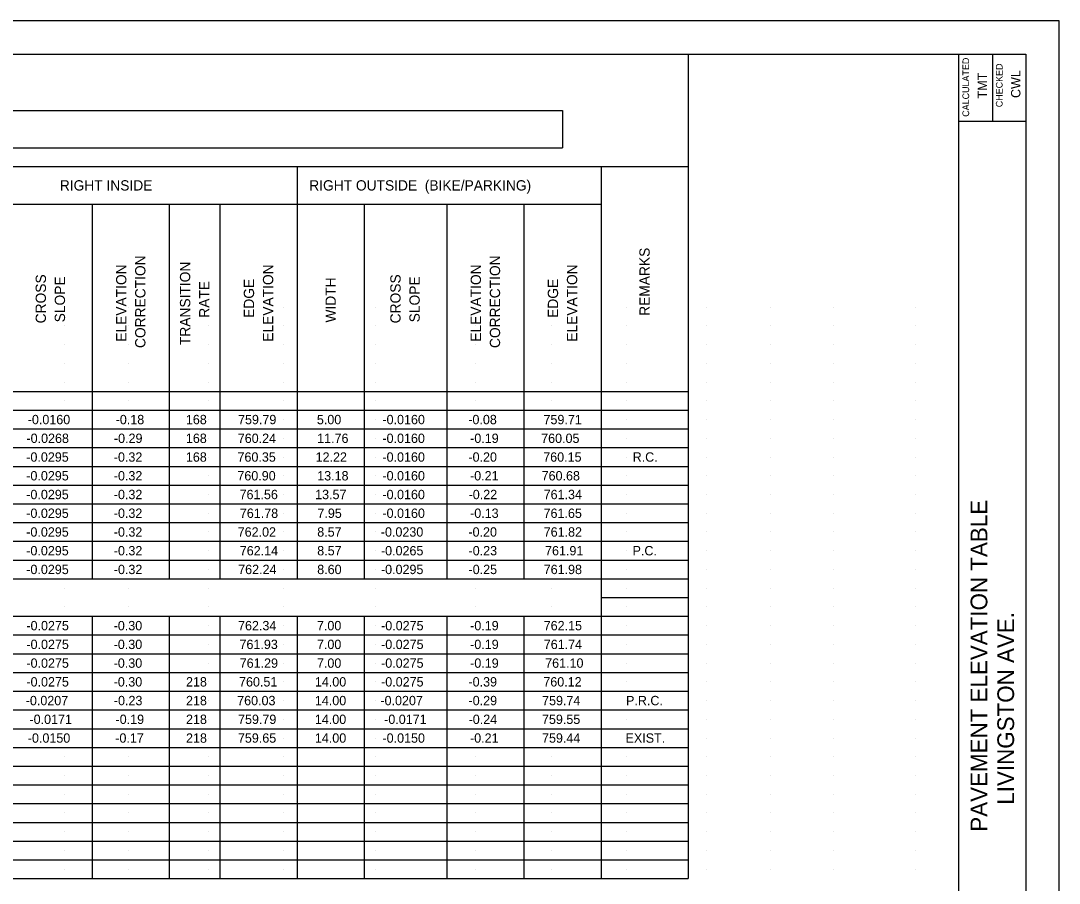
# Model space of a CAD drawing. Extents: x -15.4 to 18.6, y -12.6 to 9.4.
# Drawn here: x 3.11 to 18.64, y -3.5 to 9.39 of the extents above; entities that cross this region are included whole.
import ezdxf

# ---------------------------------------------------------------- set-up
doc = ezdxf.new("R2010")
doc.units = 0
for name, color, linetype in [('SH_Border', 7, 'Continuous'), ('SH_Cut_Line', 7, 'Continuous'), ('SH_Data', 7, 'Continuous'), ('SH_Text', 7, 'Continuous')]:
    doc.layers.add(name, color=color, linetype=linetype)

msp = doc.modelspace()

# ---------------------------------------------------------------- linework, layer by layer
at = {"layer": 'SH_Border'}
for p, q in [((17.143, -12.112), (17.143, 8.888)), ((17.643, 8.888), (17.643, 7.888)), ((17.143, 7.888), (18.143, 7.888))]:
    msp.add_line(p, q, dxfattribs=at)
msp.add_lwpolyline([(-13.357, 8.888), (18.143, 8.888), (18.143, -12.112), (-13.357, -12.112)], close=True, dxfattribs=at)
at = {"layer": 'SH_Cut_Line'}
msp.add_lwpolyline([(-15.357, -12.612), (18.643, -12.612), (18.643, 9.388), (-15.357, 9.388)], close=True, dxfattribs=at)
at = {"layer": 'SH_Data'}
for p, q in [((-10.905, 8.888), (13.093, 8.888)), ((13.093, 8.888), (13.093, -3.432)), ((-9.752, 8.048), (11.215, 8.048)), ((11.215, 8.048), (11.215, 7.488)), ((-9.752, 7.488), (11.215, 7.488)), ((-10.905, 7.208), (13.093, 7.208)), ((7.246, 7.208), (7.246, 1.048)), ((11.791, 7.208), (11.791, -3.432)), ((-10.905, 6.648), (11.791, 6.648)), ((4.182, 6.648), (4.182, 1.048)), ((5.335, 6.648), (5.335, 1.048)), ((6.093, 6.648), (6.093, 1.048)), ((8.25, 6.648), (8.25, 1.048)), ((9.486, 6.648), (9.486, 1.048)), ((10.638, 6.648), (10.638, 1.048)), ((3.768, 5.108), (3.768, 5.108)), ((4.718, 5.108), (4.718, 5.108)), ((5.918, 5.108), (5.918, 5.108)), ((7.043, 5.108), (7.043, 5.108)), ((8.418, 5.108), (8.418, 5.108)), ((9.918, 5.108), (9.918, 5.108)), ((11.043, 5.108), (11.043, 5.108)), ((12.168, 5.108), (12.168, 5.108)), ((13.368, 5.108), (13.368, 5.108)), ((14.318, 5.108), (14.318, 5.108)), ((15.268, 5.108), (15.268, 5.108)), ((16.493, 5.108), (16.493, 5.108)), ((3.768, 4.828), (3.768, 4.828)), ((4.718, 4.828), (4.718, 4.828)), ((5.918, 4.828), (5.918, 4.828)), ((7.043, 4.828), (7.043, 4.828)), ((8.418, 4.828), (8.418, 4.828)), ((9.918, 4.828), (9.918, 4.828)), ((11.043, 4.828), (11.043, 4.828)), ((12.168, 4.828), (12.168, 4.828)), ((13.368, 4.828), (13.368, 4.828)), ((14.318, 4.828), (14.318, 4.828)), ((15.268, 4.828), (15.268, 4.828)), ((16.493, 4.828), (16.493, 4.828)), ((3.768, 4.548), (3.768, 4.548)), ((4.718, 4.548), (4.718, 4.548)), ((5.918, 4.548), (5.918, 4.548)), ((7.043, 4.548), (7.043, 4.548)), ((8.418, 4.548), (8.418, 4.548)), ((9.918, 4.548), (9.918, 4.548)), ((11.043, 4.548), (11.043, 4.548)), ((12.168, 4.548), (12.168, 4.548)), ((13.368, 4.548), (13.368, 4.548)), ((14.318, 4.548), (14.318, 4.548)), ((15.268, 4.548), (15.268, 4.548)), ((16.493, 4.548), (16.493, 4.548)), ((3.768, 4.268), (3.768, 4.268)), ((4.718, 4.268), (4.718, 4.268)), ((5.918, 4.268), (5.918, 4.268)), ((7.043, 4.268), (7.043, 4.268)), ((8.418, 4.268), (8.418, 4.268)), ((9.918, 4.268), (9.918, 4.268)), ((11.043, 4.268), (11.043, 4.268)), ((12.168, 4.268), (12.168, 4.268)), ((13.368, 4.268), (13.368, 4.268)), ((14.318, 4.268), (14.318, 4.268)), ((15.268, 4.268), (15.268, 4.268)), ((16.493, 4.268), (16.493, 4.268)), ((3.768, 3.988), (3.768, 3.988)), ((4.718, 3.988), (4.718, 3.988)), ((5.918, 3.988), (5.918, 3.988)), ((7.043, 3.988), (7.043, 3.988)), ((8.418, 3.988), (8.418, 3.988)), ((9.918, 3.988), (9.918, 3.988)), ((11.043, 3.988), (11.043, 3.988)), ((12.168, 3.988), (12.168, 3.988)), ((13.368, 3.988), (13.368, 3.988)), ((14.318, 3.988), (14.318, 3.988)), ((15.268, 3.988), (15.268, 3.988)), ((16.493, 3.988), (16.493, 3.988)), ((-10.905, 3.848), (13.093, 3.848)), ((3.768, 3.708), (3.768, 3.708)), ((4.718, 3.708), (4.718, 3.708)), ((5.918, 3.708), (5.918, 3.708)), ((7.043, 3.708), (7.043, 3.708)), ((8.418, 3.708), (8.418, 3.708)), ((9.918, 3.708), (9.918, 3.708)), ((11.043, 3.708), (11.043, 3.708)), ((12.168, 3.708), (12.168, 3.708)), ((13.368, 3.708), (13.368, 3.708)), ((14.318, 3.708), (14.318, 3.708)), ((15.268, 3.708), (15.268, 3.708)), ((16.493, 3.708), (16.493, 3.708)), ((-10.905, 3.568), (13.093, 3.568)), ((3.768, 3.428), (3.768, 3.428)), ((4.718, 3.428), (4.718, 3.428)), ((5.918, 3.428), (5.918, 3.428)), ((7.043, 3.428), (7.043, 3.428)), ((8.418, 3.428), (8.418, 3.428)), ((9.918, 3.428), (9.918, 3.428)), ((11.043, 3.428), (11.043, 3.428)), ((12.168, 3.428), (12.168, 3.428)), ((13.368, 3.428), (13.368, 3.428)), ((14.318, 3.428), (14.318, 3.428)), ((15.268, 3.428), (15.268, 3.428)), ((16.493, 3.428), (16.493, 3.428)), ((-10.905, 3.288), (13.093, 3.288)), ((3.768, 3.148), (3.768, 3.148)), ((4.718, 3.148), (4.718, 3.148)), ((5.918, 3.148), (5.918, 3.148)), ((7.043, 3.148), (7.043, 3.148)), ((8.418, 3.148), (8.418, 3.148)), ((9.918, 3.148), (9.918, 3.148)), ((11.043, 3.148), (11.043, 3.148)), ((12.168, 3.148), (12.168, 3.148)), ((13.368, 3.148), (13.368, 3.148)), ((14.318, 3.148), (14.318, 3.148)), ((15.268, 3.148), (15.268, 3.148)), ((16.493, 3.148), (16.493, 3.148)), ((-10.905, 3.008), (13.093, 3.008)), ((3.768, 2.868), (3.768, 2.868)), ((4.718, 2.868), (4.718, 2.868)), ((5.918, 2.868), (5.918, 2.868)), ((7.043, 2.868), (7.043, 2.868)), ((8.418, 2.868), (8.418, 2.868)), ((9.918, 2.868), (9.918, 2.868)), ((11.043, 2.868), (11.043, 2.868)), ((12.168, 2.868), (12.168, 2.868)), ((13.368, 2.868), (13.368, 2.868)), ((14.318, 2.868), (14.318, 2.868)), ((15.268, 2.868), (15.268, 2.868)), ((16.493, 2.868), (16.493, 2.868)), ((-10.905, 2.728), (13.093, 2.728)), ((3.768, 2.588), (3.768, 2.588)), ((4.718, 2.588), (4.718, 2.588)), ((5.918, 2.588), (5.918, 2.588)), ((7.043, 2.588), (7.043, 2.588)), ((8.418, 2.588), (8.418, 2.588)), ((9.918, 2.588), (9.918, 2.588)), ((11.043, 2.588), (11.043, 2.588)), ((12.168, 2.588), (12.168, 2.588)), ((13.368, 2.588), (13.368, 2.588)), ((14.318, 2.588), (14.318, 2.588)), ((15.268, 2.588), (15.268, 2.588)), ((16.493, 2.588), (16.493, 2.588)), ((-10.905, 2.448), (13.093, 2.448)), ((3.768, 2.308), (3.768, 2.308)), ((4.718, 2.308), (4.718, 2.308)), ((5.918, 2.308), (5.918, 2.308)), ((7.043, 2.308), (7.043, 2.308)), ((8.418, 2.308), (8.418, 2.308)), ((9.918, 2.308), (9.918, 2.308)), ((11.043, 2.308), (11.043, 2.308)), ((12.168, 2.308), (12.168, 2.308)), ((13.368, 2.308), (13.368, 2.308)), ((14.318, 2.308), (14.318, 2.308)), ((15.268, 2.308), (15.268, 2.308)), ((16.493, 2.308), (16.493, 2.308)), ((-10.905, 2.168), (13.093, 2.168)), ((3.768, 2.028), (3.768, 2.028)), ((4.718, 2.028), (4.718, 2.028)), ((5.918, 2.028), (5.918, 2.028)), ((7.043, 2.028), (7.043, 2.028)), ((8.418, 2.028), (8.418, 2.028)), ((9.918, 2.028), (9.918, 2.028)), ((11.043, 2.028), (11.043, 2.028)), ((12.168, 2.028), (12.168, 2.028)), ((13.368, 2.028), (13.368, 2.028)), ((14.318, 2.028), (14.318, 2.028)), ((15.268, 2.028), (15.268, 2.028)), ((16.493, 2.028), (16.493, 2.028)), ((-10.905, 1.888), (13.093, 1.888)), ((3.768, 1.748), (3.768, 1.748)), ((4.718, 1.748), (4.718, 1.748)), ((5.918, 1.748), (5.918, 1.748)), ((7.043, 1.748), (7.043, 1.748)), ((8.418, 1.748), (8.418, 1.748)), ((9.918, 1.748), (9.918, 1.748)), ((11.043, 1.748), (11.043, 1.748)), ((12.168, 1.748), (12.168, 1.748)), ((13.368, 1.748), (13.368, 1.748)), ((14.318, 1.748), (14.318, 1.748)), ((15.268, 1.748), (15.268, 1.748)), ((16.493, 1.748), (16.493, 1.748)), ((-10.905, 1.608), (13.093, 1.608)), ((3.768, 1.468), (3.768, 1.468)), ((4.718, 1.468), (4.718, 1.468)), ((5.918, 1.468), (5.918, 1.468)), ((7.043, 1.468), (7.043, 1.468)), ((8.418, 1.468), (8.418, 1.468)), ((9.918, 1.468), (9.918, 1.468)), ((11.043, 1.468), (11.043, 1.468)), ((12.168, 1.468), (12.168, 1.468)), ((13.368, 1.468), (13.368, 1.468)), ((14.318, 1.468), (14.318, 1.468)), ((15.268, 1.468), (15.268, 1.468)), ((16.493, 1.468), (16.493, 1.468)), ((-10.905, 1.328), (13.093, 1.328)), ((3.768, 1.188), (3.768, 1.188)), ((4.718, 1.188), (4.718, 1.188)), ((5.918, 1.188), (5.918, 1.188)), ((7.043, 1.188), (7.043, 1.188)), ((8.418, 1.188), (8.418, 1.188)), ((9.918, 1.188), (9.918, 1.188)), ((11.043, 1.188), (11.043, 1.188)), ((12.168, 1.188), (12.168, 1.188)), ((13.368, 1.188), (13.368, 1.188)), ((14.318, 1.188), (14.318, 1.188)), ((15.268, 1.188), (15.268, 1.188)), ((16.493, 1.188), (16.493, 1.188)), ((-10.905, 1.048), (13.093, 1.048)), ((3.768, 0.908), (3.768, 0.908)), ((4.718, 0.908), (4.718, 0.908)), ((5.918, 0.908), (5.918, 0.908)), ((7.043, 0.908), (7.043, 0.908)), ((8.418, 0.908), (8.418, 0.908)), ((9.918, 0.908), (9.918, 0.908)), ((11.043, 0.908), (11.043, 0.908)), ((12.168, 0.908), (12.168, 0.908)), ((13.368, 0.908), (13.368, 0.908)), ((14.318, 0.908), (14.318, 0.908)), ((15.268, 0.908), (15.268, 0.908)), ((16.493, 0.908), (16.493, 0.908)), ((3.768, 0.628), (3.768, 0.628)), ((4.718, 0.628), (4.718, 0.628)), ((5.918, 0.628), (5.918, 0.628)), ((7.043, 0.628), (7.043, 0.628)), ((8.418, 0.628), (8.418, 0.628)), ((9.918, 0.628), (9.918, 0.628)), ((11.043, 0.628), (11.043, 0.628)), ((11.791, 0.768), (13.093, 0.768)), ((12.168, 0.628), (12.168, 0.628)), ((13.368, 0.628), (13.368, 0.628)), ((14.318, 0.628), (14.318, 0.628)), ((15.268, 0.628), (15.268, 0.628)), ((16.493, 0.628), (16.493, 0.628)), ((-10.905, 0.488), (13.093, 0.488)), ((4.182, 0.488), (4.182, -3.432)), ((5.335, 0.488), (5.335, -3.432)), ((6.093, 0.488), (6.093, -3.432)), ((7.246, 0.488), (7.246, -3.432)), ((8.25, 0.488), (8.25, -3.432)), ((9.486, 0.488), (9.486, -3.432)), ((10.638, 0.488), (10.638, -3.432)), ((3.768, 0.348), (3.768, 0.348)), ((4.718, 0.348), (4.718, 0.348)), ((5.918, 0.348), (5.918, 0.348)), ((7.043, 0.348), (7.043, 0.348)), ((8.418, 0.348), (8.418, 0.348)), ((9.918, 0.348), (9.918, 0.348)), ((11.043, 0.348), (11.043, 0.348)), ((12.168, 0.348), (12.168, 0.348)), ((13.368, 0.348), (13.368, 0.348)), ((14.318, 0.348), (14.318, 0.348)), ((15.268, 0.348), (15.268, 0.348)), ((16.493, 0.348), (16.493, 0.348)), ((-10.905, 0.208), (13.093, 0.208)), ((3.768, 0.068), (3.768, 0.068)), ((4.718, 0.068), (4.718, 0.068)), ((5.918, 0.068), (5.918, 0.068)), ((7.043, 0.068), (7.043, 0.068)), ((8.418, 0.068), (8.418, 0.068)), ((9.918, 0.068), (9.918, 0.068)), ((11.043, 0.068), (11.043, 0.068)), ((12.168, 0.068), (12.168, 0.068)), ((13.368, 0.068), (13.368, 0.068)), ((14.318, 0.068), (14.318, 0.068)), ((15.268, 0.068), (15.268, 0.068)), ((16.493, 0.068), (16.493, 0.068)), ((-10.905, -0.072), (13.093, -0.072)), ((3.768, -0.212), (3.768, -0.212)), ((4.718, -0.212), (4.718, -0.212)), ((5.918, -0.212), (5.918, -0.212)), ((7.043, -0.212), (7.043, -0.212)), ((8.418, -0.212), (8.418, -0.212)), ((9.918, -0.212), (9.918, -0.212)), ((11.043, -0.212), (11.043, -0.212)), ((12.168, -0.212), (12.168, -0.212)), ((13.368, -0.212), (13.368, -0.212)), ((14.318, -0.212), (14.318, -0.212)), ((15.268, -0.212), (15.268, -0.212)), ((16.493, -0.212), (16.493, -0.212)), ((-10.905, -0.352), (13.093, -0.352)), ((3.768, -0.492), (3.768, -0.492)), ((4.718, -0.492), (4.718, -0.492)), ((5.918, -0.492), (5.918, -0.492)), ((7.043, -0.492), (7.043, -0.492)), ((8.418, -0.492), (8.418, -0.492)), ((9.918, -0.492), (9.918, -0.492)), ((11.043, -0.492), (11.043, -0.492)), ((12.168, -0.492), (12.168, -0.492)), ((13.368, -0.492), (13.368, -0.492)), ((14.318, -0.492), (14.318, -0.492)), ((15.268, -0.492), (15.268, -0.492)), ((16.493, -0.492), (16.493, -0.492)), ((-10.905, -0.632), (13.093, -0.632)), ((3.768, -0.772), (3.768, -0.772)), ((4.718, -0.772), (4.718, -0.772)), ((5.918, -0.772), (5.918, -0.772)), ((7.043, -0.772), (7.043, -0.772)), ((8.418, -0.772), (8.418, -0.772)), ((9.918, -0.772), (9.918, -0.772)), ((11.043, -0.772), (11.043, -0.772)), ((12.168, -0.772), (12.168, -0.772)), ((13.368, -0.772), (13.368, -0.772)), ((14.318, -0.772), (14.318, -0.772)), ((15.268, -0.772), (15.268, -0.772)), ((16.493, -0.772), (16.493, -0.772)), ((-10.905, -0.912), (13.093, -0.912)), ((3.768, -1.052), (3.768, -1.052)), ((4.718, -1.052), (4.718, -1.052)), ((5.918, -1.052), (5.918, -1.052)), ((7.043, -1.052), (7.043, -1.052)), ((8.418, -1.052), (8.418, -1.052)), ((9.918, -1.052), (9.918, -1.052)), ((11.043, -1.052), (11.043, -1.052)), ((12.168, -1.052), (12.168, -1.052)), ((13.368, -1.052), (13.368, -1.052)), ((14.318, -1.052), (14.318, -1.052)), ((15.268, -1.052), (15.268, -1.052)), ((16.493, -1.052), (16.493, -1.052)), ((-10.905, -1.192), (13.093, -1.192)), ((3.768, -1.332), (3.768, -1.332)), ((4.718, -1.332), (4.718, -1.332)), ((5.918, -1.332), (5.918, -1.332)), ((7.043, -1.332), (7.043, -1.332)), ((8.418, -1.332), (8.418, -1.332)), ((9.918, -1.332), (9.918, -1.332)), ((11.043, -1.332), (11.043, -1.332)), ((12.168, -1.332), (12.168, -1.332)), ((13.368, -1.332), (13.368, -1.332)), ((14.318, -1.332), (14.318, -1.332)), ((15.268, -1.332), (15.268, -1.332)), ((16.493, -1.332), (16.493, -1.332)), ((-10.905, -1.472), (13.093, -1.472)), ((3.768, -1.612), (3.768, -1.612)), ((4.718, -1.612), (4.718, -1.612)), ((5.918, -1.612), (5.918, -1.612)), ((7.043, -1.612), (7.043, -1.612)), ((8.418, -1.612), (8.418, -1.612)), ((9.918, -1.612), (9.918, -1.612)), ((11.043, -1.612), (11.043, -1.612)), ((12.168, -1.612), (12.168, -1.612)), ((13.368, -1.612), (13.368, -1.612)), ((14.318, -1.612), (14.318, -1.612)), ((15.268, -1.612), (15.268, -1.612)), ((16.493, -1.612), (16.493, -1.612)), ((-10.905, -1.752), (13.093, -1.752)), ((3.768, -1.892), (3.768, -1.892)), ((4.718, -1.892), (4.718, -1.892)), ((5.918, -1.892), (5.918, -1.892)), ((7.043, -1.892), (7.043, -1.892)), ((8.418, -1.892), (8.418, -1.892)), ((9.918, -1.892), (9.918, -1.892)), ((11.043, -1.892), (11.043, -1.892)), ((12.168, -1.892), (12.168, -1.892)), ((13.368, -1.892), (13.368, -1.892)), ((14.318, -1.892), (14.318, -1.892)), ((15.268, -1.892), (15.268, -1.892)), ((16.493, -1.892), (16.493, -1.892)), ((-10.905, -2.032), (13.093, -2.032)), ((3.768, -2.172), (3.768, -2.172)), ((4.718, -2.172), (4.718, -2.172)), ((5.918, -2.172), (5.918, -2.172)), ((7.043, -2.172), (7.043, -2.172)), ((8.418, -2.172), (8.418, -2.172)), ((9.918, -2.172), (9.918, -2.172)), ((11.043, -2.172), (11.043, -2.172)), ((12.168, -2.172), (12.168, -2.172)), ((13.368, -2.172), (13.368, -2.172)), ((14.318, -2.172), (14.318, -2.172)), ((15.268, -2.172), (15.268, -2.172)), ((16.493, -2.172), (16.493, -2.172)), ((-10.905, -2.312), (13.093, -2.312)), ((3.768, -2.452), (3.768, -2.452)), ((4.718, -2.452), (4.718, -2.452)), ((5.918, -2.452), (5.918, -2.452)), ((7.043, -2.452), (7.043, -2.452)), ((8.418, -2.452), (8.418, -2.452)), ((9.918, -2.452), (9.918, -2.452)), ((11.043, -2.452), (11.043, -2.452)), ((12.168, -2.452), (12.168, -2.452)), ((13.368, -2.452), (13.368, -2.452)), ((14.318, -2.452), (14.318, -2.452)), ((15.268, -2.452), (15.268, -2.452)), ((16.493, -2.452), (16.493, -2.452)), ((-10.905, -2.592), (13.093, -2.592)), ((3.768, -2.732), (3.768, -2.732)), ((4.718, -2.732), (4.718, -2.732)), ((5.918, -2.732), (5.918, -2.732)), ((7.043, -2.732), (7.043, -2.732)), ((8.418, -2.732), (8.418, -2.732)), ((9.918, -2.732), (9.918, -2.732)), ((11.043, -2.732), (11.043, -2.732)), ((12.168, -2.732), (12.168, -2.732)), ((13.368, -2.732), (13.368, -2.732)), ((14.318, -2.732), (14.318, -2.732)), ((15.268, -2.732), (15.268, -2.732)), ((16.493, -2.732), (16.493, -2.732)), ((-10.905, -2.872), (13.093, -2.872)), ((3.768, -3.012), (3.768, -3.012)), ((4.718, -3.012), (4.718, -3.012)), ((5.918, -3.012), (5.918, -3.012)), ((7.043, -3.012), (7.043, -3.012)), ((8.418, -3.012), (8.418, -3.012)), ((9.918, -3.012), (9.918, -3.012)), ((11.043, -3.012), (11.043, -3.012)), ((12.168, -3.012), (12.168, -3.012)), ((13.368, -3.012), (13.368, -3.012)), ((14.318, -3.012), (14.318, -3.012)), ((15.268, -3.012), (15.268, -3.012)), ((16.493, -3.012), (16.493, -3.012)), ((-10.905, -3.152), (13.093, -3.152)), ((3.768, -3.292), (3.768, -3.292)), ((4.718, -3.292), (4.718, -3.292)), ((5.918, -3.292), (5.918, -3.292)), ((7.043, -3.292), (7.043, -3.292)), ((8.418, -3.292), (8.418, -3.292)), ((9.918, -3.292), (9.918, -3.292)), ((11.043, -3.292), (11.043, -3.292)), ((12.168, -3.292), (12.168, -3.292)), ((13.368, -3.292), (13.368, -3.292)), ((14.318, -3.292), (14.318, -3.292)), ((15.268, -3.292), (15.268, -3.292)), ((16.493, -3.292), (16.493, -3.292)), ((-10.905, -3.432), (13.093, -3.432))]:
    msp.add_line(p, q, dxfattribs=at)

# ---------------------------------------------------------------- texts
for s, height, p in [('CALCULATED', 0.1, (17.296, 7.953)), ('CHECKED', 0.1, (17.796, 8.096)), ('TMT', 0.14, (17.563, 8.227)), ('CWL', 0.14, (18.063, 8.234)), ('PAVEMENT ELEVATION TABLE', 0.25, (17.568, -2.732)), ('          LIVINGSTON AVE.           ', 0.25, (17.968, -3.257))]:
    msp.add_text(s, height=height, rotation=90, dxfattribs=at).set_placement(p)
at = {"layer": 'SH_Text'}
for s, height, p in [('RIGHT INSIDE ', 0.154, (3.698, 6.851)), ('RIGHT OUTSIDE  (BIKE/PARKING)', 0.154, (7.428, 6.851)), ('-0.0160', 0.14, (3.218, 3.358)), ('-0.18', 0.14, (4.533, 3.358)), ('168', 0.14, (5.583, 3.358)), ('759.79', 0.14, (6.363, 3.358)), ('5.00', 0.14, (7.542, 3.358)), ('-0.0160', 0.14, (8.522, 3.358)), ('-0.08', 0.14, (9.806, 3.358)), ('759.71', 0.14, (10.931, 3.358)), ('-0.0268', 0.14, (3.199, 3.078)), ('-0.29', 0.14, (4.507, 3.078)), ('168', 0.14, (5.583, 3.078)), ('760.24', 0.14, (6.359, 3.078)), ('11.76', 0.14, (7.546, 3.078)), ('-0.0160', 0.14, (8.522, 3.078)), ('-0.19', 0.14, (9.834, 3.078)), ('760.05', 0.14, (10.896, 3.078)), ('-0.0295', 0.14, (3.196, 2.798)), ('-0.32', 0.14, (4.505, 2.798)), ('168', 0.14, (5.583, 2.798)), ('760.35', 0.14, (6.355, 2.798)), ('12.22', 0.14, (7.523, 2.798)), ('-0.0160', 0.14, (8.522, 2.798)), ('-0.20', 0.14, (9.808, 2.798)), ('760.15', 0.14, (10.927, 2.798)), ('R.C.', 0.14, (12.264, 2.798)), ('-0.0295', 0.14, (3.196, 2.518)), ('-0.32', 0.14, (4.505, 2.518)), ('760.90', 0.14, (6.353, 2.518)), ('13.18', 0.14, (7.547, 2.518)), ('-0.0160', 0.14, (8.522, 2.518)), ('-0.21', 0.14, (9.832, 2.518)), ('760.68', 0.14, (10.903, 2.518)), ('-0.0295', 0.14, (3.196, 2.238)), ('-0.32', 0.14, (4.505, 2.238)), ('761.56', 0.14, (6.386, 2.238)), ('13.57', 0.14, (7.516, 2.238)), ('-0.0160', 0.14, (8.522, 2.238)), ('-0.22', 0.14, (9.811, 2.238)), ('761.34', 0.14, (10.933, 2.238)), ('-0.0295', 0.14, (3.196, 1.958)), ('-0.32', 0.14, (4.505, 1.958)), ('761.78', 0.14, (6.39, 1.958)), ('7.95', 0.14, (7.55, 1.958)), ('-0.0160', 0.14, (8.522, 1.958)), ('-0.13', 0.14, (9.833, 1.958)), ('761.65', 0.14, (10.932, 1.958)), ('-0.0295', 0.14, (3.196, 1.678)), ('-0.32', 0.14, (4.505, 1.678)), ('762.02', 0.14, (6.358, 1.678)), ('8.57', 0.14, (7.547, 1.678)), ('-0.0230', 0.14, (8.498, 1.678)), ('-0.20', 0.14, (9.808, 1.678)), ('761.82', 0.14, (10.934, 1.678)), ('-0.0295', 0.14, (3.196, 1.398)), ('-0.32', 0.14, (4.505, 1.398)), ('762.14', 0.14, (6.389, 1.398)), ('8.57', 0.14, (7.547, 1.398)), ('-0.0265', 0.14, (8.5, 1.398)), ('-0.23', 0.14, (9.81, 1.398)), ('761.91', 0.14, (10.954, 1.398)), ('P.C.', 0.14, (12.263, 1.398)), ('-0.0295', 0.14, (3.196, 1.118)), ('-0.32', 0.14, (4.505, 1.118)), ('762.24', 0.14, (6.365, 1.118)), ('8.60', 0.14, (7.547, 1.118)), ('-0.0295', 0.14, (8.5, 1.118)), ('-0.25', 0.14, (9.81, 1.118)), ('761.98', 0.14, (10.934, 1.118)), ('-0.0275', 0.14, (3.198, 0.278)), ('-0.30', 0.14, (4.503, 0.278)), ('762.34', 0.14, (6.363, 0.278)), ('7.00', 0.14, (7.543, 0.278)), ('-0.0275', 0.14, (8.502, 0.278)), ('-0.19', 0.14, (9.834, 0.278)), ('762.15', 0.14, (10.934, 0.278)), ('-0.0275', 0.14, (3.198, -0.002)), ('-0.30', 0.14, (4.503, -0.002)), ('761.93', 0.14, (6.385, -0.002)), ('7.00', 0.14, (7.543, -0.002)), ('-0.0275', 0.14, (8.502, -0.002)), ('-0.19', 0.14, (9.834, -0.002)), ('761.74', 0.14, (10.935, -0.002)), ('-0.0275', 0.14, (3.198, -0.282)), ('-0.30', 0.14, (4.503, -0.282)), ('761.29', 0.14, (6.388, -0.282)), ('7.00', 0.14, (7.543, -0.282)), ('-0.0275', 0.14, (8.502, -0.282)), ('-0.19', 0.14, (9.834, -0.282)), ('761.10', 0.14, (10.956, -0.282)), ('-0.0275', 0.14, (3.198, -0.562)), ('-0.30', 0.14, (4.503, -0.562)), ('218', 0.14, (5.585, -0.562)), ('760.51', 0.14, (6.378, -0.562)), ('14.00', 0.14, (7.512, -0.562)), ('-0.0275', 0.14, (8.502, -0.562)), ('-0.39', 0.14, (9.809, -0.562)), ('760.12', 0.14, (10.928, -0.562)), ('-0.0207', 0.14, (3.188, -0.842)), ('-0.23', 0.14, (4.506, -0.842)), ('218', 0.14, (5.585, -0.842)), ('760.03', 0.14, (6.35, -0.842)), ('14.00', 0.14, (7.512, -0.842)), ('-0.0207', 0.14, (8.492, -0.842)), ('-0.29', 0.14, (9.81, -0.842)), ('759.74', 0.14, (10.91, -0.842)), ('P.R.C.', 0.14, (12.165, -0.842)), ('-0.0171', 0.14, (3.244, -1.122)), ('-0.19', 0.14, (4.531, -1.122)), ('218', 0.14, (5.585, -1.122)), ('759.79', 0.14, (6.363, -1.122)), ('14.00', 0.14, (7.512, -1.122)), ('-0.0171', 0.14, (8.548, -1.122)), ('-0.24', 0.14, (9.811, -1.122)), ('759.55', 0.14, (10.908, -1.122)), ('-0.0150', 0.14, (3.219, -1.402)), ('-0.17', 0.14, (4.527, -1.402)), ('218', 0.14, (5.585, -1.402)), ('759.65', 0.14, (6.361, -1.402)), ('14.00', 0.14, (7.512, -1.402)), ('-0.0150', 0.14, (8.523, -1.402)), ('-0.21', 0.14, (9.832, -1.402)), ('759.44', 0.14, (10.909, -1.402)), ('EXIST.', 0.14, (12.158, -1.402))]:
    msp.add_text(s, height=height, dxfattribs=at).set_placement(p)
for s, p in [('REMARKS', (12.519, 4.978)), ('CORRECTION', (4.978, 4.497)), ('TRANSITION', (5.648, 4.541)), ('CORRECTION', (10.282, 4.497)), ('ELEVATION', (4.693, 4.591)), ('ELEVATION', (6.889, 4.591)), ('ELEVATION', (9.996, 4.591)), ('ELEVATION', (11.435, 4.591)), ('CROSS', (3.49, 4.866)), ('SLOPE', (3.776, 4.881)), ('RATE', (5.934, 4.95)), ('EDGE', (6.603, 4.948)), ('WIDTH', (7.825, 4.878)), ('CROSS', (8.794, 4.866)), ('SLOPE', (9.08, 4.881)), ('EDGE', (11.149, 4.948))]:
    msp.add_text(s, height=0.154, rotation=90, dxfattribs=at).set_placement(p)

doc.saveas('drawing.dxf')
